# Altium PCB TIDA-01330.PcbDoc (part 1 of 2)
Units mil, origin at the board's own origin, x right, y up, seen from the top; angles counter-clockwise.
Board outline 4950 x 3950 mil, 2 copper layers (Top Layer, Bottom Layer), stack 62.2 mil thick; 84 components, 65 nets, 268 pads, 356 vias.
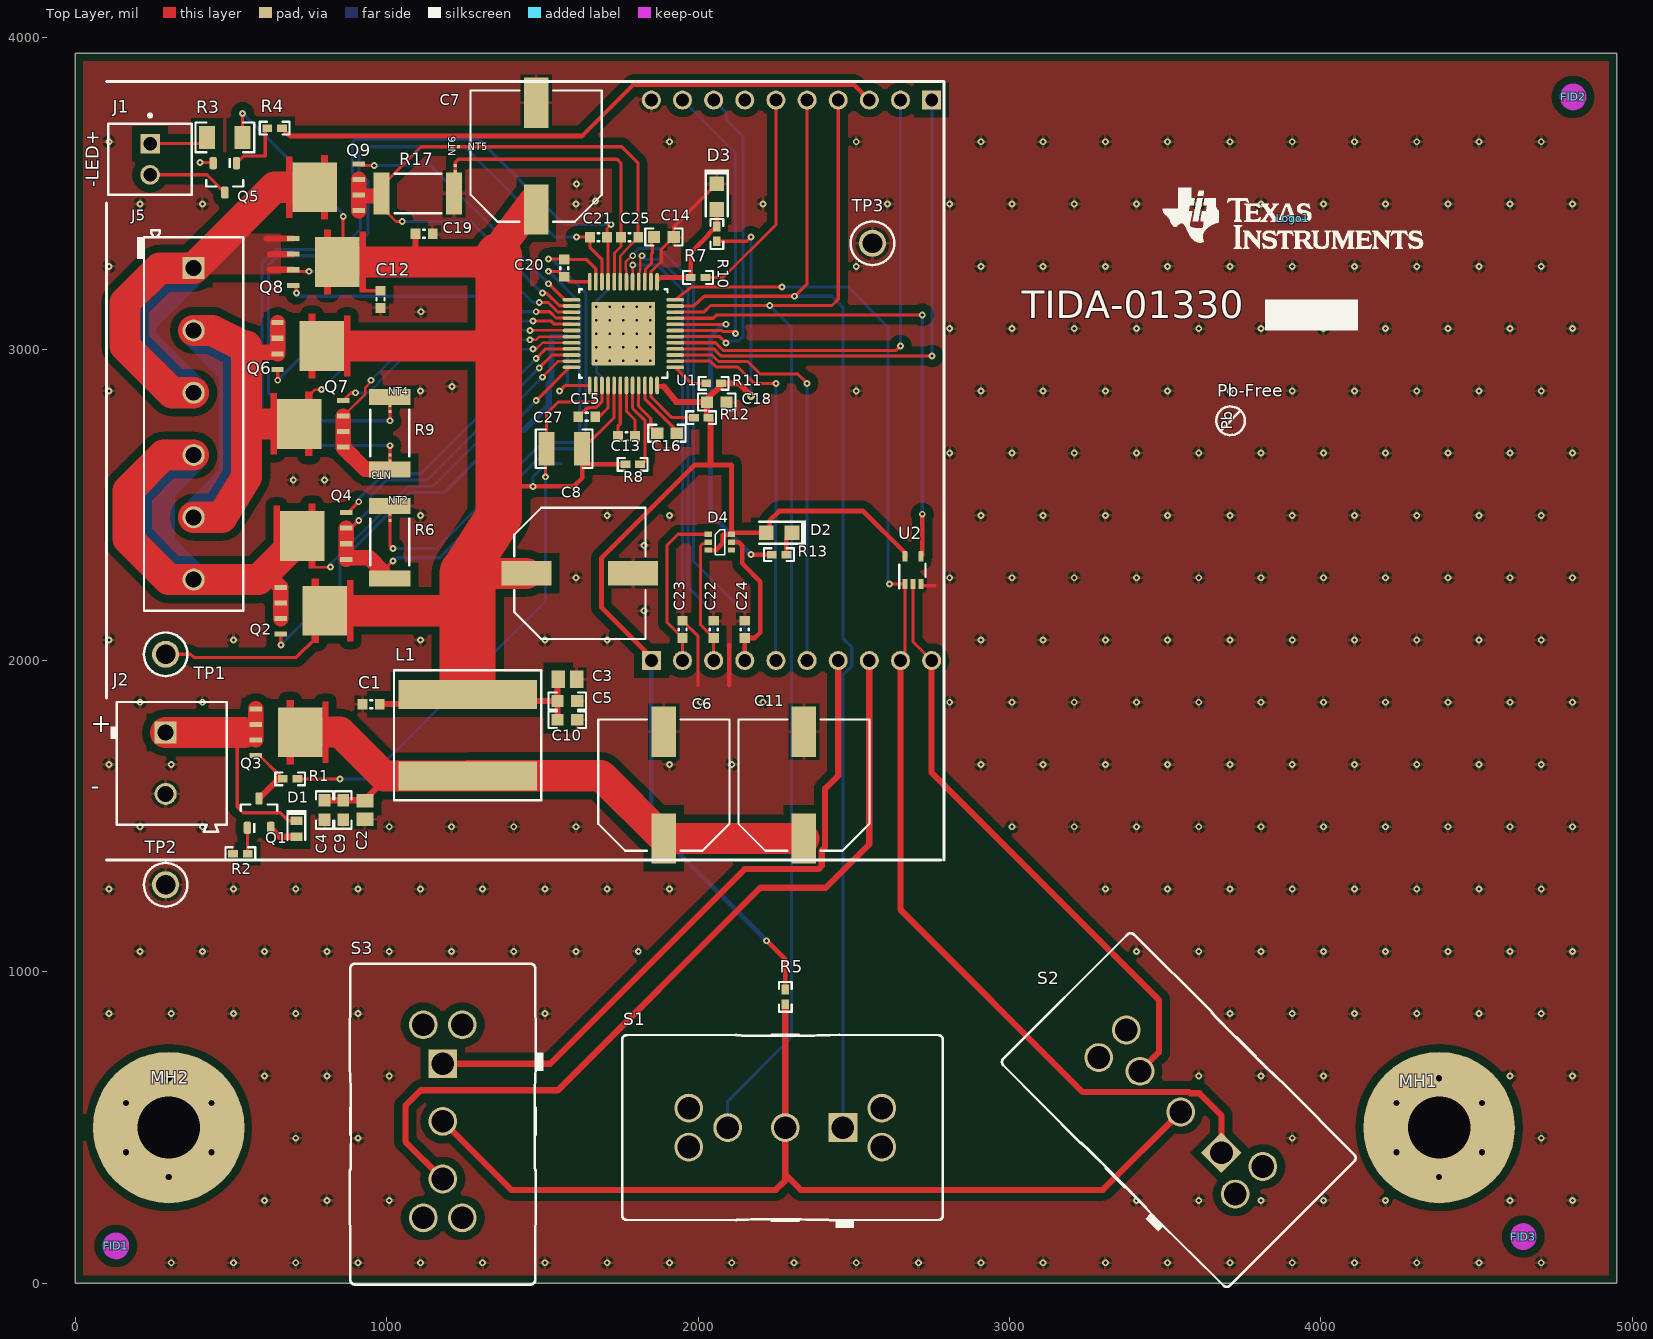
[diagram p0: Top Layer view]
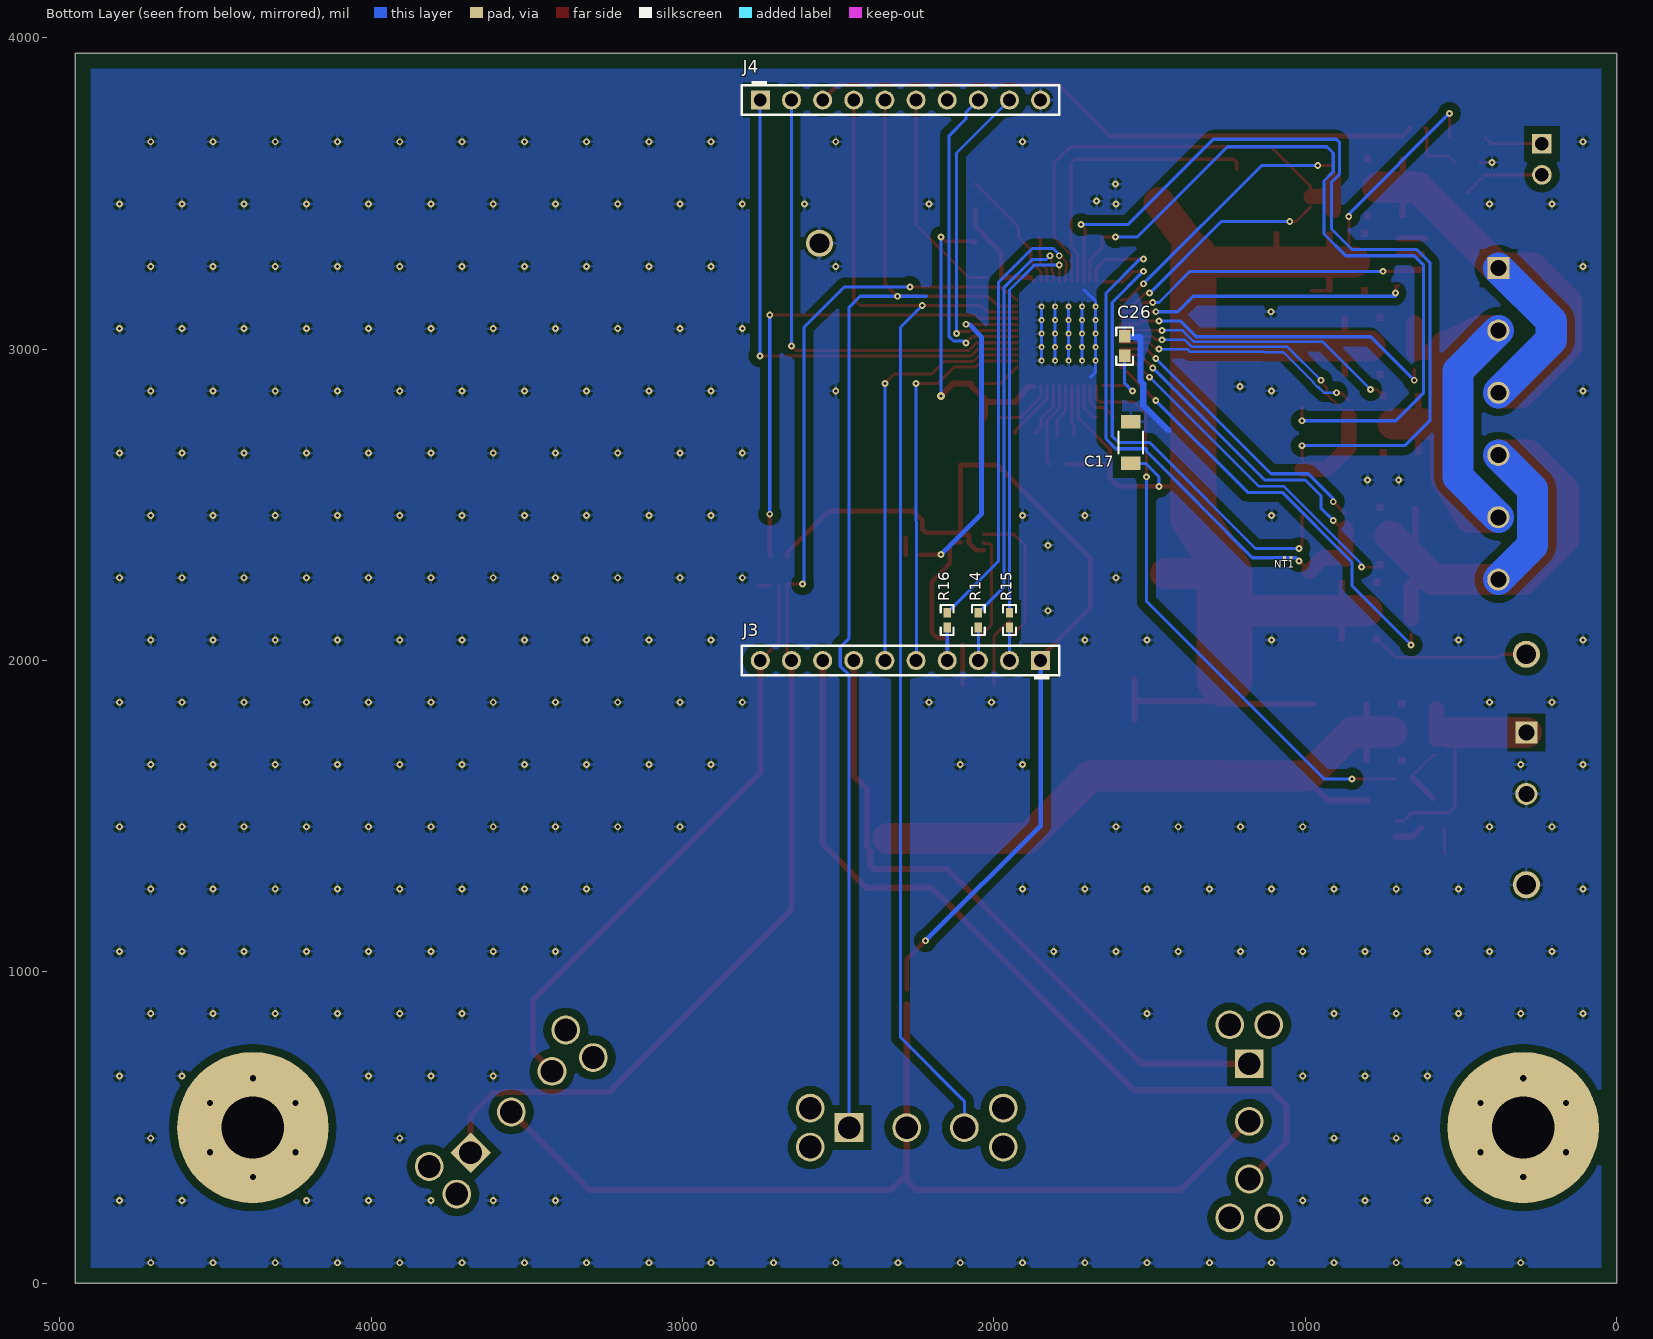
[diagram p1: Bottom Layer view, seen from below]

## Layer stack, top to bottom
Top Solder: solder mask 0.4, Solder Resist, Dk 3.5
Top Layer: signal copper 3.6
Dielectric1: core 55, FR-4, Dk 4.8
Bottom Layer: signal copper 3.6
Bottom Solder: solder mask 0.4, Solder Resist, Dk 3.5

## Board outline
0,0 0,3950 4950,3950 4950,0

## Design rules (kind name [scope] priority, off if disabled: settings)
AcuteAngle [All] p1: minimum=4.50000000000000E+0001 checktracksonly=FALSE
AssemblyTestPointUsage [All] p1: valid=2
BoardOutlineClearance BoardOutlineClearance_MountingHoles [OnCopper and InComponentClass('Mounting Holes')] p1: gap=40
BoardOutlineClearance BoardOutlineClearance_Poly [OnCopper and IsPoly] p2: gap=25
BoardOutlineClearance [OnCopper and Not InComponentClass('Logo') and not InComponentClass('FiducialMark') and not InRegion(1000,500,4000,800) and not InPoly] p3: gap=75
Clearance Clearance_Keepouts [((IsTrack Or IsArc) And Not InPoly) And IsFree and IsKeepOut vs ((IsTrack Or IsArc) And Not InPoly) And IsFree and IsKeepOut] p1: gap=0
Clearance Clearance_Poly [InPolygon] p2: gap=25
Clearance [All] p3: gap=7.87
ComponentClearance ComponentClearance_MountingHoles_FiducialMarks [InComponentClass('Mounting Holes') vs InComponentClass('FiducialMark')] p1: gap=50 collisioncheckmode=3 verticalgap=10 showdistances=FALSE
ComponentClearance ComponentClearance_Shunt [InComponentClass('Header') vs InComponentClass('Shunt')] p2: gap=0 collisioncheckmode=3 verticalgap=0 showdistances=FALSE
ComponentClearance ComponentClearance_Logo [InComponentClass('Logo')] p3: gap=50 collisioncheckmode=3 verticalgap=10 showdistances=FALSE
ComponentClearance ComponentClearance_ScrewToNut [(HasFootprint('NY PMS 440 0025 PH')) vs (HasFootprint('Keystone_1902C'))] p4: gap=5 collisioncheckmode=3 verticalgap=10 showdistances=FALSE
ComponentClearance ComponentClearance_MountingHoles [InComponentClass('Mounting Holes')] p5: gap=250 collisioncheckmode=3 verticalgap=100000 showdistances=FALSE
ComponentClearance ComponentClearance_SmallPassives [HasFootprint('0201*') or HasFootprint('0402*') or HasFootprint('0508') or HasFootprint('0603*') or HasFootprint('0612') or HasFootprint('0805*') or HasFootprint('0815*') or HasFootprint('0830*') or HasFootprint('1206*') or HasFootprint('1210*') or HasFootprint('1808*') or HasFootprint('1812*') or HasFootprint('1825*') or HasFootprint('2010*') or HasFootprint('2220*') or HasFootprint('2225*') or HasFootprint('2512*') or HasFootprint('2728*') or HasFootprint('3518*') vs HasFootprint('0201*') or HasFootprint('0402*') or HasFootprint('0508') or HasFootprint('0603*') or HasFootprint('0612') or HasFootprint('0805*') or HasFootprint('0815*') or HasFootprint('0830*') or HasFootprint('1206*') or HasFootprint('1210*') or HasFootprint('1808*') or HasFootprint('1812*') or HasFootprint('1825*') or HasFootprint('2010*') or HasFootprint('2220*') or HasFootprint('2225*') or HasFootprint('2512*') or HasFootprint('2728*') or HasFootprint('3518*')] p6: gap=14.96 collisioncheckmode=3 verticalgap=10 showdistances=FALSE
ComponentClearance ComponentClearance_THtoSMT [IsThruComponent vs IsSMTComponent] p7: gap=40 collisioncheckmode=3 verticalgap=30 showdistances=FALSE
ComponentClearance ComponentClearance_THtoTH [IsThruComponent vs IsThruComponent] p8: gap=30 collisioncheckmode=3 verticalgap=30 showdistances=FALSE
ComponentClearance [InComponent('NT1')] p9: gap=0 collisioncheckmode=3 verticalgap=10 showdistances=FALSE
DiffPairsRouting [All] p1: maxlimit=100 minlimit=10 mostfreqgap=10 toplayer_minwidth=10 toplayer_maxwidth=15 toplayer_prefwidth=15 bottomlayer_minwidth=10 bottomlayer_maxwidth=15 bottomlayer_prefwidth=15 maxuncoupledlength=1000
FabricationTestPointUsage TestPointUsage [All] p1: valid=2 allowmultiple=FALSE
FabricationTestpoint Testpoint [All] p1: side=3 testpointundercomponent=TRUE minsize=40 maxsize=100 preferedsize=60 minholesize=0 maxholesize=40 preferedholesize=32 testpointgrid=1 allowsidetop=TRUE allowsidebottom=TRUE usegrid=TRUE gridtolerance=0.01
FanoutControl Fanout_LCC [IsLCC] p1: bgadir=Out bgaviamode=Centered fanoutstyle=Auto fanoutdirection=Alternating viagrid=1 // Fanout_LCC (Default Rule)
FanoutControl Fanout_BGA [IsBGA] p2: bgadir=Out bgaviamode=Centered fanoutstyle=Auto fanoutdirection=Alternating viagrid=1 // Fanout_BGA (Default Rule)
FanoutControl Fanout_Default [All] p4: bgadir=Out bgaviamode=Centered fanoutstyle=Auto fanoutdirection=Alternating viagrid=1 // Fanout_Default (Default Rule)
FanoutControl Fanout_Small [(CompPinCount < 5)] p5: bgadir=Out bgaviamode=Centered fanoutstyle=Auto fanoutdirection=OutThenIn viagrid=1 // Fanout_Small (Default Rule)
HoleSize [All] p1: absolutevalues=TRUE maxlimit=251 minlimit=7.87 maxpercent=80.000 minpercent=20.000
MinimumAnnularRing MinimumAnnularRing_ThermalPadVias [IsVia and InAnyComponent] p1: minimumring=5.91
MinimumAnnularRing [All] p2: minimumring=8
MinimumSolderMaskSliver MinimumSolderMaskSliver_Logo [InComponentClass('Logo') vs InComponentClass('Logo')] p1: minsoldermaskwidth=0.7
MinimumSolderMaskSliver [All] p2: minsoldermaskwidth=3.94
PlaneConnect [All] p1: planeconnectstyle=Relief reliefexpansion=10 reliefentries=4 reliefconductorwidth=10 reliefairgap=10
PolygonConnect [All] p1: connectstyle=Relief reliefconductorwidth=10 reliefentries=4 polygonreliefangle="90 Angle" airgapwidth=10
RoomDefinition "TIDA 01330 Schematic" [InComponentClass('TIDA 01330 Schematic')] p1: confinementstyle=ConfineOut formatcopy=TRUE lockcomponents=FALSE outline 5530,7230 5540,7230 5540,7240 5530,7240
RoutingVias ThermalPadVias [IsVia and InAnyComponent] p1: holewidth=7.87 width=19.68 viastyle="Through Hole" minholewidth=7.87 minwidth=19.68 maxholewidth=12.99 maxwidth=23.62
RoutingVias [All] p2: holewidth=16 width=34 viastyle="Through Hole" minholewidth=7.87 minwidth=26 maxholewidth=40 maxwidth=65
SilkToBoardRegionClearance [Not ((IsComment or IsDesignator) And (Hide <> 'False')) and not InRegion(1000,500,4000,800)] p1:
SilkToSilkClearance SilkToSilkClearance_Pb-FreeLogo [(HasFootprint('Pb-Free_Overlay_Medium') OR HasFootprint('Pb-Free_Overlay_Small')) vs (HasFootprint('Pb-Free_Overlay_Medium') OR HasFootprint('Pb-Free_Overlay_Small'))] p1: silktosilkclearance=0
SilkToSilkClearance [All] p2: silktosilkclearance=4
SilkToSolderMaskClearance SilkToComponentPadClearance [IsPad and InAnycomponent] p1: minsilkscreentomaskgap=5 clearancetoexposedcopper=TRUE
SilkToSolderMaskClearance "Silk to Solder Mask Opening" [All] p2: minsilkscreentomaskgap=4 clearancetoexposedcopper=FALSE
SolderMaskExpansion [All] p1: expansion=1.97
Width [All] p1: maxlimit=100 minlimit=6 preferedwidth=10 checkconnectedcopper=TRUE
15 further rules are at their usual default settings.

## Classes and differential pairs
component class FiducialMark: FID1 FID2 FID3 FID?
component class TID_Hardware: FID1 FID2 FID3 FID? Logo1 Logo? MH1 MH2 MH? Pb-Free ZZ?
component class Logo: Logo1
component class "TIDA 01330 Schematic": C1 C2 C3 C4 C5 C6 C7 C8 C9 C10 C11 C12 C13 C14 C15 C16 C17 C18 C19 C20 C21 C22 C23 C24 C25 C26 C27 C28 C29 D1 D2 D3 D4 J1 J2 J3 J4 J5 L1 NT1 NT2 NT3 NT4 NT5 NT6 Q1 Q2 Q3 Q4 Q5 Q6 Q7 Q8 Q9 R1 R2 R3 R4 R5 R6 R7 R8 R9 R10 R11 R12 R13 R14 R15 R16 R17 S1 S2 S3 TP1 TP2 TP3 U1 U2
differential pair S1: +S1_P -S1_N
differential pair S2: +S2_P -S2_N
differential pair S3: +S3_P -S3_N

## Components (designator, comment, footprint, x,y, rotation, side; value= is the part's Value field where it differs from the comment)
C1 "UMK107AB7105KA-T" 0603L 950,1860 r180 top
C2 "GRM21BR71H105KA12L" 0805L 930,1520 r270 top
C3 "GRM21BR71H105KA12L" 0805L 1580,1940 r0 top
C4 "C1608X7R1H104K080AA" 0603 800,1520 r270 top
C5 "C1608X7R1H104K080AA" 0603 1580,1870 r0 top
C6 "EEE-FT1H331AP" SM_RADIAL_G 1890,1600 r90 top
C7 "EEE-FT1H331AP" SM_RADIAL_G 1480,3620 r90 top
C8 "EEE-FT1H331AP" SM_RADIAL_G 1620,2280 r0 top
C9 "C1608X7R1H103K080AA" 0603 860,1520 r270 top
C10 "C1608X7R1H103K080AA" 0603 1580,1810 r0 top
C11 "EEE-FT1H331AP" SM_RADIAL_G 2340,1600 r90 top
C12 "UMK107AB7105KA-T" 0603L 980,3160 r270 top
C13 "C0603C473K1RACTU" 0603L 1770,2720 r180 top
C14 "C1608X7R1C105K080AC" 0603 1890,3360 r180 top
C15 "C0603C473K1RACTU" 0603L 1642.44,2782.44 r0 top
C16 "C1608X7R1C105K080AC" 0603 1900,2730 r0 top
C17 "GRM31CR71H475KA12L" 1206_180 1560,2700 r90 bottom
C18 "C1608X7R1C105K080AC" 0603 2060,2830 r180 top
C19 "UMK107AB7105KA-T" 0603L 1120,3370 r0 top
C20 "GRM188R71C102KA01D" 0603L 1570,3260 r270 top
C21 "GRM188R71C102KA01D" 0603L 1680,3360 r180 top
C22 "GRM188R71C222KA01D" 0603L 2050,2100 r90 top
C23 "GRM188R71C222KA01D" 0603L 1950,2100 r90 top
C24 "GRM188R71C222KA01D" 0603L 2150,2100 r90 top
C25 "GRM188R71C102KA01D" 0603L 1780,3360 r180 top
C26 "C1608X7R1C105K080AC" 0603 1580,3010 r90 bottom
C27 "GRM32ER72A225KA35L" 1210_270 1570,2680 r0 top
D1 "CD0603-S0180" Diode_0603 710,1460 r270 top
D2 "LTST-C170KRKT" LED_LTST-C170_Red 2260,2410 r0 top
D3 "LTST-C170KGKT" LTST-C170KGKT_Green 2060,3490 r90 top
D4 "BAT54CDW-7-F" SOT-363 2070,2380 r0 top
FID1 "Fiducial" Fiducial10-20 130,120 r0 top
FID2 "Fiducial" Fiducial10-20 4810,3810 r0 top
FID3 "Fiducial" Fiducial10-20 4650,150 r0 top
J1 "282834-2" TEC_282834-2 240,3610 r270 top
J2 "691 101 710 002" Wurth_691101710002 290,1670 r270 top
J3 "SSW-110-01-T-S" Samtec_SSW-110-x1-x-S 2300,2000 r0 bottom
J4 "SSW-110-01-T-S" Samtec_SSW-110-x1-x-S 2300,3800 r180 bottom
J5 "1729160" Phoenix_1729160 380,2760 r270 top
L1 "XAL1010-222MEB" XAL1010 1260,1760 r90 top
Logo1 "Texas Instruments" TI_Stacked_Overlay_Small 3910,3420 r0 top
MH1 "MTG_Pads" MTGP_6-32_Washer 4380,500 r0 top
MH2 "MTG_Pads" MTGP_6-32_Washer 300,500 r0 top
NT1 "Net-Tie" Net-Tie_10mil 1056.31,2330 r180 bottom net-tie
NT2 "Net-Tie" Net-Tie_10mil 1010,2460 r90 top net-tie
NT3 "Net-Tie" Net-Tie_10mil 1010,2650 r270 top net-tie
NT4 "Net-Tie" Net-Tie_10mil 1010,2810 r90 top net-tie
NT5 "Net-Tie" Net-Tie_10mil 1220,3650 r180 top net-tie
NT6 "Net-Tie" Net-Tie_10mil 1220,3580 r270 top net-tie
Pb-Free "Pb-Free Symbol" Pb-Free_Overlay_Small 3710,2770 r90 top
Q1 "BC846BLT1G" SOT-23 590,1510 r90 top
Q2 "SQJ858AEP" PowerPAK_SO-8L 770,2160 r0 top
Q3 "SQJ422EP-T1-GE3" PowerPAK_SO-8L 690,1770 r0 top
Q4 "SQJ858AEP" PowerPAK_SO-8L 760,2400 r180 top
Q5 "BC846BLT1G" SOT-23 480,3550 r270 top
Q6 "SQJ858AEP" PowerPAK_SO-8L 760,3010 r0 top
Q7 "SQJ858AEP" PowerPAK_SO-8L 750,2760 r180 top
Q8 "SQJ858AEP" PowerPAK_SO-8L 810,3280 r0 top
Q9 "SQJ858AEP" PowerPAK_SO-8L 800,3520 r180 top
R1 "CRCW040210K0JNED" 0402 690,1620 r180 top
R2 "CRCW040210K0JNED" 0402 530,1380 r180 top
R3 "CRCW1206330RJNEA" 1206 480,3680 r180 top
R4 "CRCW04021K00JNED" 0402 640,3710 r180 top
R5 "CRCW0402330RJNED" 0402 2280,920 r270 top
R6 "CRA2512-FZ-R015ELF" 2512 1010,2380 r270 top
R7 "CRCW040256R0JNED" 0402 2000,3230 r0 top
R8 "CRCW0402100RFKED" 0402 1790,2630 r180 top
R9 "CRA2512-FZ-R015ELF" 2512 1010,2730 r270 top
R10 "CRCW0402470RJNED" 0402 2060,3370 r270 top
R11 "CRCW040210K0JNED" 0402 2050,2890 r0 top
R12 "CRCW040210K0JNED" 0402 2010,2780 r0 top
R13 "CRCW0402470RJNED" 0402 2260,2340 r0 top
R14 "CRCW040256R0JNED" 0402 2050,2130 r90 bottom
R15 "CRCW040256R0JNED" 0402 1950,2130 r90 bottom
R16 "CRCW040256R0JNED" 0402 2150,2130 r90 bottom
R17 "CRA2512-FZ-R015ELF" 2512 1100,3500 r180 top
S1 "7105J3V3QE2" SW_710XJ3V3 2280,500 r180 top
S2 "7105J3V3QE2" SW_710XJ3V3 3550,550 r135 top
S3 "7105J3V3QE2" SW_710XJ3V3 1180,520 r270 top
TP1 "5005" Keystone5005 290,2020 r0 top
TP2 "5006" Keystone5006 290,1280 r0 top
TP3 "5006" Keystone5006 2560,3340 r0 top
U1 "DRV83053EPHPRQ1" PHP0048G_N 1760,3050 r180 top
U2 "SN74AHC1G00DCKR" DCK0005A_N 2690,2290 r90 top

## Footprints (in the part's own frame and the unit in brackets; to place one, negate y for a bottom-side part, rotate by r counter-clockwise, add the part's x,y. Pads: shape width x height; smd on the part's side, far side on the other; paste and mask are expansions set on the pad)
0402 [mm] "0402 from SM-752 data"
  rect 0.8x0.6 smd: 1(-0.6,0) 2(0.6,0)
  silkscreen extent -1.22,-0.52 1.22,0.52, body extent -0.55,-0.3 0.55,0.3, height 0.6
0603 [mm] "0603 from SM-752 data"
  rect 1x0.95 smd: 1(-0.8,0) 2(0.8,0)
  silkscreen extent -1.52,-0.69 1.52,0.69, body extent -0.87,-0.47 0.87,0.47, height 1
0603L [mm] "0603 from SM-752 data"
  rect 0.8x0.85 smd: 1(-0.7,0) 2(0.7,0)
  silkscreen extent -0.07,-0.33 0.07,0.33, body extent -0.87,-0.47 0.87,0.47, height 1
0805L [mm] "0805 from SM-752 data"
  rect 1.1x1.4 smd: 1(-0.75,0) 2(0.75,0)
  body extent -1.1,-0.72 1.1,0.72, height 1.45
1206 [mm] "1206 from SM-752 data"
  rect 1.3x1.85 smd: 1(-1.45,0) 2(1.45,0)
  silkscreen extent -2.4,-1.21 2.4,1.21, body extent -1.7,-0.9 1.7,0.9, height 1.35
1206_180 [mm] "1206_180"
  rect 1.1x1.6 smd: 1(-1.7,0) 2(1.7,0)
  silkscreen extent -0.9,-1 0.9,1, body extent -1.75,-0.95 1.75,0.95, height 1.8
1210_270 [mm] "1210"
  rect 1.3x2.7 smd: 1(-1.45,0) 2(1.45,0)
  silkscreen extent -2.32,-1.57 2.32,1.57, body extent -1.7,-1.35 1.7,1.35, height 2.7
2512 [mm] "Chip Resistor, Body 6.3x3.2mm, IPC Medium Density"
  rect 1.3x3.4 smd: 1(-2.95,0) 2(2.95,0)
  silkscreen extent -1.9,-1.6 1.9,1.6, body extent -3.22,-1.67 3.22,1.67, height 0.71
DCK0005A_N [mm] "SOT353, 5-Leads, Body 2x1.3mm, Pitch 0.65mm, Lead Span 2.1mm, IPC Medium Density"
  rrect25% 0.85x0.4 smd: 1(-1.125,0.65) 2(-1.125,0) 3(-1.125,-0.65) 4(1.125,-0.65) 5(1.125,0.65)
  silkscreen extent -1.48,-1.02 0.55,1.1, body extent -1.14,-1 1.14,1, height 0.95
Diode_0603 [mm] "Based on Bourns recommended land pattern Rev 10/09"
  rect 0.7x1 smd: 1(-0.65,0) 2(0.65,0)
  silkscreen extent -1.5,-0.8 0.9,0.8, body extent -0.9,-0.5 0.9,0.5, height 0.85
Fiducial10-20 [mm]
  round 1 smd mask+0.5: 1(0,0)
  Top Layer keep-out circle w1.178: c0,0 r0.5
Keystone5005 [mil] "Keystone Compact loops"
  round 87 hole 63: 1(0,0)
  silkscreen extent -70,-70 70,70, body extent -63,-63 62,63, height 225
Keystone5006 [mil] "Keystone Compact loops"
  round 87 hole 63: 1(0,0)
  silkscreen extent -70,-70 70,70, body extent -63,-63 62,63, height 225
LED_LTST-C170_Red [mm] "LITE-ON"
  rect 1.2x1.2 smd: 1(-1.05,0) 2(1.05,0)
  silkscreen extent -1.6,-1 2.2,1, body extent -1.05,-0.67 1.05,0.67, height 1.1
LTST-C170KGKT_Green [mm] "LITE-ON"
  rect 1.2x1.2 smd: 1(-1.05,0) 2(1.05,0)
  silkscreen extent -1.6,-1 2.2,1, body extent -1.05,-0.67 1.05,0.67, height 1.1
MTGP_6-32_Washer [mm] "6-32 Mounting Hole, Plated, for Flat Washer"
  round 12.35 hole 5.08: 1(0,0)
Net-Tie_10mil [mil] "10mil net tie, no solder mask opening, no solder paste"
  rect 10x10 smd paste-5 mask-5: 1(-10,0) 2(10,0)
  Top Layer region: -6,5 6,5 6,-5 -6,-5
Pb-Free_Overlay_Small [mil]
  silkscreen extent -46,-46 46,46
Phoenix_1729160 [mm] "Phoenix Contact"
  rect 1.8x1.8 hole 1.3 paste+0: 1(-12.7,0)
  round 1.8 hole 1.3 paste+0: 2(-7.62,0) 3(-2.54,0) 4(2.54,0) 5(7.62,0) 6(12.7,0)
  silkscreen extent -15.81,-4.63 15.24,4.05, body extent -15.81,-4.05 15.24,4.05, height 10.01
PHP0048G_N [mm] "QFP, 48-Leads, Body 7x7mm, Pitch 0.5mm, Thermal Pad 5.17X5.17mm, IPC Medium Density"
  oval 1.45x0.3 smd: 1(-4.225,2.75) 2(-4.225,2.25) 3(-4.225,1.75) 4(-4.225,1.25) 5(-4.225,0.75) 6(-4.225,0.25) 7(-4.225,-0.25) 8(-4.225,-0.75) 9(-4.225,-1.25) 10(-4.225,-1.75) 11(-4.225,-2.25) 12(-4.225,-2.75) 25(4.225,-2.75) 26(4.225,-2.25) 27(4.225,-1.75) 28(4.225,-1.25) 29(4.225,-0.75) 30(4.225,-0.25) 31(4.225,0.25) 32(4.225,0.75) 33(4.225,1.25) 34(4.225,1.75) 35(4.225,2.25) 36(4.225,2.75)
  oval 0.3x1.45 smd: 13(-2.75,-4.225) 14(-2.25,-4.225) 15(-1.75,-4.225) 16(-1.25,-4.225) 17(-0.75,-4.225) 18(-0.25,-4.225) 19(0.25,-4.225) 20(0.75,-4.225) 21(1.25,-4.225) 22(1.75,-4.225) 23(2.25,-4.225) 24(2.75,-4.225) 37(2.75,4.225) 38(2.25,4.225) 39(1.75,4.225) 40(1.25,4.225) 41(0.75,4.225) 42(0.25,4.225) 43(-0.25,4.225) 44(-0.75,4.225) 45(-1.25,4.225) 46(-1.75,4.225) 47(-2.25,4.225) 48(-2.75,4.225)
  rrect2% 5.17x5.17 smd: 49(0,0)
  silkscreen extent -3.6,-3.6 3.6,3.6, body extent -4.51,-4.51 4.51,4.51, height 1.2
PowerPAK_SO-8L [mm] "based on Vishay recommended land pattern Document 63818 Feb 7, 2012"
  rect 1x0.41 smd: 1(-2.805,1.905) 2(-2.805,0.635) 3(-2.805,-0.635) 4(-2.805,-1.905)
  rect 3.63x4.061 smd: 5(0.805,0)
  Top Layer region: 2.615,-2.5 3.125,-2.5 3.125,2.5 2.615,2.5
  Top Layer region: -0.297,2.03 0.298,2.03 0.298,2.64 -0.297,2.64
  Top Layer region: -0.298,-2.64 0.298,-2.64 0.298,-2.03 -0.298,-2.03
  body extent -3.07,-2.57 3.08,2.57, height 1.21
Samtec_SSW-110-x1-x-S [mm] "Receptacle, 2.54mm, 10x1, TH"
  rect 1.55x1.55 hole 1.04: 1(-11.43,0)
  round 1.55 hole 1.04: 2(-8.89,0) 3(-6.35,0) 4(-3.81,0) 5(-1.27,0) 6(1.27,0) 7(3.81,0) 8(6.35,0) 9(8.89,0) 10(11.43,0)
  silkscreen extent -12.95,-1.21 12.95,1.55, body extent -12.95,-1.21 12.95,1.21, height 8.51
SM_RADIAL_G [mm] "10 x 10.2mm:  Panasonic G"
  rect 4.1x2 smd: 1(-4.35,0) 2(4.35,0)
  silkscreen extent -5.35,-5.35 5.35,5.35, body extent -5.25,-5.25 5.25,5.25, height 10.5
SOT-23 [mm] "SOT23, 3-Leads, Body 2.9x1.3mm, Pitch 0.95mm, Lead Span 2.5mm, IPC Medium Density"
  rrect50% 1x0.6 smd: 1(-1.2,0.95) 2(-1.2,-0.95) 3(1.2,0)
  silkscreen extent -1.63,-1.5 0.7,1.5, body extent -1.16,-1.45 1.21,1.45, height 1
SOT-363 [mm]
  rect 0.6x0.42 smd mask+0.051: 1(-0.95,0.65) 2(-0.95,0) 3(-0.95,-0.65) 4(0.95,-0.65) 5(0.95,0) 6(0.95,0.65)
  silkscreen extent -0.38,-1.02 0.38,1.02, body extent -1.1,-1.1 1.1,1.1, height 1.12
SW_710XJ3V3 [mm] "TH, 3-Leads, Body 15.75x8.13mm, Pitch 4.7mm"
  rect 2.35x2.35 hole 1.85: 1(-4.7,0)
  round 2.35 hole 1.85: 2(0,0) 3(4.7,0) S1(-7.875,1.59) S2(-7.875,-1.59) S3(7.875,-1.59) S4(7.875,1.59)
  silkscreen extent -12.85,-7.57 13.31,8.2, body extent -12.85,-7.57 13.31,7.58, height 26.51
TEC_282834-2 [mm] "TEC"
  rect 1.6x1.6 hole 1.1: 1(-1.27,0)
  round 1.6 hole 1.1: 2(1.27,0)
  silkscreen extent -3.66,-3.4 2.9,3.4, body extent -2.77,-3.25 2.77,3.25, height 10.01
TI_Stacked_Overlay_Small [mil]
  silkscreen extent -418,-98 418,98
Wurth_691101710002 [mm] "Terminal Block, 5 mm, 2x1, TH"
  rect 1.8x1.8 hole 1.3: 1(-2.5,0)
  round 1.8 hole 1.3: 2(2.5,0)
  silkscreen extent -5,-4.5 5.6,5, body extent -5.6,-4 5.6,5, height 12.5
XAL1010 [mm] "COILCRAFT"
  rect 2.38x11.31 smd: 1(-3.325,0) 2(3.325,0)
  silkscreen extent -5.3,-6 5.3,6, body extent -5.25,-5.9 5.25,5.9, height 10

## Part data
C1 C12 C19: "CAP, CERM, 1 µF, 50 V, +/- 10%, X7R, 0603"
C2 C3: "CAP, CERM, 1uF, 50V, +/-10%, X7R, 0805"
C4 C5: "CAP, CERM, 0.1 µF, 50 V, +/- 10%, X7R, 0603"
C6 C7 C8 C11: library part EEE-FC1H221P, "CAP, AL, 330 µF, 50 V, +/- 20%, 0.3 ohm, SMD"
C9 C10: "CAP, CERM, 0.01 µF, 50 V, +/- 10%, X7R, 0603"
C13 C15: library part GRM188R72A104KA35D, "CAP, CERM, 0.047uF, 100V, +/-10%, X7R, 0603"
C14 C16 C18 C26: "CAP, CERM, 1 µF, 16 V, +/- 10%, X7R, 0603"
C17: "CAP, CERM, 4.7 µF, 50 V, +/- 10%, X7R, 1206"
C20 C21 C25: "CAP, CERM, 1000pF, 16V, +/-10%, X7R, 0603"
C22 C23 C24: "CAP, CERM, 2200pF, 16V, +/-10%, X7R, 0603"
C27: "CAP, CERM, 2.2 µF, 100 V, +/- 10%, X7R, 1210"
D1: "Diode, Switching, 90V, 0.1A, 0603 Diode"
D2: "LED, Red, SMD"
D3: "LED, Green, SMD"
D4: "Diode, Schottky, 30 V, 0.2 A, SOT-363"
FID1 FID2 FID3: "Fiducial mark.  There is nothing to buy or mount."
J1: "Terminal Block, 2x1, 2.54mm, TH"
J2: "Terminal Block, 5 mm, 2x1, Tin, TH"
J3 J4: "Receptacle, 2.54mm, 10x1, Tin, TH"
J5: "Terminal Block, 6x1, 5.08mm, Th"
L1: "Inductor, Shielded, Composite, 2.2 µH, 32 A, 0.00255 ohm, SMD"
Logo1: library part TI_Logo, "Texas Instrument Corporate Signature"
MH1 MH2: library part "Mounting Hole (Imperial) with Pads", "PCB Mounting Hole"
NT1 NT2 NT3 NT4 NT5 NT6: "Single point connection between nets."
Pb-Free: library part Pb-Free
Q1 Q5: library part "BC846BLT1G, ON Semiconductor", "Transistor, NPN, 65V, 0.1A, SOT-23"
Q2 Q4 Q6 Q7 Q8 Q9: library part SQJ858AEP-T1-GE3, "MOSFET, N-CH, 40 V, 58 A, PowerPAK_SO-8L"
Q3: "MOSFET, N-CH, 40 V, 75 A, PowerPAK_SO-8L"
R1 R2 R11 R12: "RES, 10 k, 5%, 0.063 W, 0402"
R3: "RES, 330, 5%, 0.25 W, 1206"
R4: "RES, 1.0 k, 5%, 0.063 W, 0402"
R5: "RES, 330, 5%, 0.063 W, 0402"
R6 R9 R17: "RES, 0.015, 1%, 3 W, 2512"
R7 R14 R15 R16: "RES, 56, 5%, 0.063 W, 0402"
R8: "RES, 100, 1%, 0.063 W, 0402"
R10 R13: "RES, 470, 5%, 0.063 W, 0402"
S1 S2 S3: "Switch, SPDT, Mom-Off-Mom, 3 Pos, 5 A, 28 VDC, TH"
TP1: "Test Point, Compact, Red, TH"
TP2 TP3: "Test Point, Compact, Black, TH"
U1: "Three Phase Automotive Gate Driver with Three Integrated Current Shunt Amplifiers and Voltage Regulator, PHP0048G"
U2: "SINGLE 2-INPUT POSITIVE-NAND GATE, DCK0005A (SOT-5)"

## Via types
v1: diameter 22, hole 10, Top Layer to Bottom Layer, 318 vias
v2: diameter 19.68, hole 7.87, Top Layer to Bottom Layer, 25 vias
v3: diameter 39.37, hole 19.68, Top Layer to Bottom Layer, 12 vias
v4: diameter 26, hole 10, Top Layer to Bottom Layer, 1 vias

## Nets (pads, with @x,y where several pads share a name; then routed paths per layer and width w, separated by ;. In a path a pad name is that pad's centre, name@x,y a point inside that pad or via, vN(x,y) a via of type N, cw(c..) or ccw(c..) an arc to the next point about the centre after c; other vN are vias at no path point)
3P3V: C18.2 D2.1 D4.3 D4.6 J3.1 R5.1 R10.2 R11.2 R12.2 U1.48 U2.5 | length 4368
  Top Layer w10: R10.2@2060,3346.38 2156.38,3346.38 v1(2170,3360)
  Top Layer w15: J3.1@1850,2000 1850,2010 1690,2170 1690,2330 1987.82,2627.82 2040,2627.82 2107.4,2627.82 D4.6@2107.4,2405.59 ; U1.48@1870,2880 1890,2880 ; D4.3@2032.6,2354.41 2056.22,2354.41 2080.22,2378.41 2080.22,2403.64 D4.6@2105.45,2403.64 ; R10.2@2060,3346.38 R10.2@2063.62,3342.76 ; D4.6@2111.81,2410 D2.1@2218.66,2410 2230,2421.34 2230,2450 2260,2480 2530,2480 2664.41,2345.59 U2.5@2664.41,2334.29 ; v1(2220,1100) 2280,1040 R5.1@2280,943.62
  Top Layer w20: 1890,2880 1930,2830 C18.2@2028.5,2830 2028.5,2785.12 R12.2@2033.62,2780 2040,2773.62 2040,2627.82 ; C18.2@2028.5,2838.5 R11.2@2076.38,2886.38 ; R11.2@2073.62,2890 2130,2890 v4(2170,2850)
  Bottom Layer w10: v4(2170,2850) v1(2170,3360)
  Bottom Layer w15: J3.1@1850,2000 1850,1470 v1(2220,1100)
AH: J3.5 U1.2 | length 1241.8
  Top Layer w10: U1.2@1926.34,2961.42 2038.99,2961.42 2057.9,2942.5 2127.5,2942.5 2180,2890 v1(2250,2890)
  Bottom Layer w10: J3.5@2248.58,2001.42 v1(2250,2890)
AL: J3.6 U1.3 | length 1355.2
  Top Layer w10: U1.3@1926.34,2981.1 2044.58,2981.1 2065.3,2960.38 2159.62,2960.38 2200,2920 2320,2920 v1(2350,2890) v1@2350,2893.76
  Bottom Layer w10: J3.6@2350,2000 v1(2350,2890)
AVDD: C14.2 U1.15 | length 159.1
  Top Layer w10: U1.15@1828.9,3216.34 1829.8,3217.24 1829.8,3246.76 1830.71,3247.66 1830.71,3255.99 1850,3275.28 1850,3306.24 1853.87,3310.11 1853.87,3329.89 1850,3333.76 1850,3351.5 C14.2@1858.5,3360
BACK: J4.4 S1.3 U1.10 | length 3934.2
  Top Layer w10: U1.10@1926.34,3118.9 2020,3120 2040,3140 2430,3140 2450,3160 J4.4@2450,3800
  Bottom Layer w10: S1.3@2094.96,500 2094.96,584.96 2300,790 2300,3070 v1(2230,3140)
BH: J4.1 U1.4 | length 1654.7
  Top Layer w10: U1.4@1926.34,3000.79 2050.17,3000.79 2072.71,2978.25 v1(2751.75,2978.25)
  Bottom Layer w10: v1(2751.75,2978.25) J4.1@2751.75,3798.25
BL: J4.2 U1.5 | length 1529.5
  Top Layer w10: U1.5@1926.34,3020.47 2055.76,3020.47 2080.11,2996.13 2636.13,2996.13 v1(2650,3010)
  Bottom Layer w10: v1(2650,3010) J4.2@2650,3800
CH: J4.8 U1.6 | length 1033
  Top Layer w10: U1.6@1926.34,3040.16 2069.84,3040.16 v1(2090,3020)
  Bottom Layer w10: J4.8@2050,3800 2090,3760 2090,3739.15 2143.87,3685.28 2143.87,3040.11 2129.89,3026.13 2096.13,3026.13 v1(2090,3020)
CL: J4.9 U1.7 | length 1009.5
  Top Layer w10: U1.7@1926.34,3059.84 2076.39,3059.84 2080.11,3056.13 v1@2113.87,3056.13
  Bottom Layer w10: J4.9@1950,3800 2120,3630 v1(2120,3050)
DOWN: J3.8 S3.3 | length 2712.7
  Top Layer w20: S3.3@1180,334.96 1060,454.96 1060,570 1110,620 1550,620 2200,1270 2410,1270 2550,1410 J3.8@2550,2000
DVDD: C16.2 U1.46 | length 196.2
  Top Layer w10: U1.46@1828.9,2883.66 1828.9,2841.1 1931.5,2738.5 C16.2@1931.5,2730
EN_GATE: R11.1 U1.1 | length 121.5
  Top Layer w10: U1.1@1926.34,2941.73 1978.07,2890 R11.1@2026.38,2890
FWD: J4.5 S1.1 U1.11 | length 3962.9
  Top Layer w10: U1.11@1926.34,3138.58 1984.33,3138.58 1985.75,3140 2020,3170 v1(2310,3170) 2350,3210 J4.5@2350,3800
  Bottom Layer w10: 2217.17,3170 2430,3170 2465.04,3134.96 2465.04,2071.73 2493.39,2043.39 2493.39,1982.03 2465.04,1953.68 S1.1@2465.04,500
GH_A: Q2.4 U1.36 | length 1382.2
  Top Layer w10: v1@659.57,2050.43 Q2.4@659.57,2085 ; v1(1480,2834.72) 1587.01,2941.73 U1.36@1593.66,2941.73
  Bottom Layer w10: v1(660,2050) 850,2240 850,2316.14 1073.86,2540 1185.28,2540 v1(1480,2834.72)
GH_B: Q6.4 U1.29 | length 1061.9
  Top Layer w10: Q6.4@649.57,2935 650,2934.57 v1(650,2900) ; v1(1470,3090) 1528.35,3090 1537.92,3080.43 1592.76,3080.43 U1.29@1593.66,3079.53
  Bottom Layer w10: v1(650,2900) 790,3040 1350,3040 1400,3090 v1(1470,3090)
GH_C: Q8.4 U1.28 | length 952.3
  Top Layer w10: Q8.4@699.57,3205 710,3194.57 ; v1(710,3180) Q8.4@710,3204.57 ; v1(1480,3120) 1523.63,3120 1543.51,3100.12 1592.76,3100.12 U1.28@1593.66,3099.21
  Bottom Layer w10: v1@710,3170 1360,3170 1410,3120 v1(1480,3120)
GL_A: Q4.4 U1.33 | length 946.9
  Top Layer w10: Q4.4@870.43,2475 875,2475 v1(910,2510) ; v1(1480,2970) 1510.79,3000.79 U1.33@1593.66,3000.79
  Bottom Layer w10: v1(910,2510) 910,2520 990,2600 1110,2600 v1(1480,2970)
GL_B: Q7.4 U1.32 | length 811.4
  Top Layer w8: v1(1470,3000) 1480,3000 1500.47,3020.47 U1.32@1593.66,3020.47
  Top Layer w10: Q7.4@860.43,2835 885.43,2860 v1(900,2860)
  Bottom Layer w8: v1(900,2860) 940,2860 957.13,2877.13 959.47,2877.13 972.87,2890.53 972.87,2892.87 1070,2990 1130,2990 1131.38,2991.38 1370.14,2991.38 1378.76,3000 v1(1470,3000)
GL_C: Q9.4 U1.25 | length 864.1
  Top Layer w10: Q9.4@910.43,3595 915.43,3590 v1(960,3590) ; v1(1520,3210) 1571.73,3158.27 U1.25@1593.66,3158.27
  Bottom Layer w10: v1(960,3590) 1140,3590 v1(1520,3210)
GND: C1.2 C2.2 C3.2 C4.2 C5.2 C6.2 C7.2 C8.2 C9.2 C10.2 C11.2 C12.2 C14.1 C16.1 C17.2 C18.1 C19.2 C22.2 C23.2 C24.2 C26.2 D3.2 J2.2 J4.10 NT2.2 NT4.2 NT6.2 Q5.2 R2.2 R6.1 R9.1 R17.1 TP2.1 TP3.1 U1.14 U1.45 U1.49 U2.3 | length 2403.4
  Top Layer w10: v1(400,3600) Q5.2@439.84,3600 ; U1.45@1809.21,2883.66 1809.21,2816.06 1847.87,2777.4 1847.87,2750.63 C16.1@1868.5,2730 ; U1.14@1848.58,3216.34 1848.58,3248.58 1881.5,3281.5 1881.5,3320 C14.1@1921.5,3360 1921.5,3392.83 D3.2@2060,3531.34 ; C23.2@1950,2127.56 2000,2077.56 2000,1920 ; U2.3@2715.59,2245.71 2721.3,2240 2760,2240
  Top Layer w15: 2100,1921.47 2100,2050
  Bottom Layer w10: 1690,2910 1673.39,2926.61 v2(1673.39,2963.39) v2(1673.39,3006.69) v2(1673.39,3050) v2(1673.39,3093.31) v2(1673.39,3136.61) 1673.39,3153.39 1710,3190 ; v2(1716.69,2963.39) v2(1716.69,3006.69) v2(1716.69,3050) v2(1716.69,3093.31) v2(1716.69,3136.61) ; v2(1760,2963.39) v2(1760,3006.69) v2(1760,3050) v2(1760,3093.31) v2(1760,3136.61) ; v2(1803.31,2963.39) v2(1803.31,3006.69) v2(1803.31,3050) v2(1803.31,3093.31) v2(1803.31,3136.61) ; v2(1846.61,2963.39) v2(1846.61,3006.69) v2(1846.61,3050) v2(1846.61,3093.31) v2(1846.61,3136.61)
  Bottom Layer w20: 1440,2740 1520,2820 1520,2889.17 1528.87,2898.04 1528.87,3038.87 C26.2@1577.38,3038.87
  other v1: 308,66 508,66 708,66 908,66 1108,66 1308,66 1508,66 1708,66 1908,66 2108,66 2308,66 2508,66 2708,66 2908,66 3108,66 3308,66 3508,66 3708,66 3908,66 4108,66 4308,66 4508,66 4708,66 608,266 808,266 1008,266 3408,266 3608,266 3808,266 4008,266 4208,266 4608,266 4808,266 708,466 908,466 3908,466 4708,466 608,666 808,666 1008,666 3608,666 3808,666 4008,666 4608,666 4808,666 108,866 308,866 508,866 708,866 908,866 1508,866 3708,866 3908,866 4108,866 4308,866 4508,866 4708,866 208,1066 408,1066 608,1066 808,1066 1008,1066 1208,1066 1408,1066 1608,1066 1808,1066 3408,1066 3608,1066 3808,1066 4008,1066 4208,1066 4408,1066 4608,1066 4808,1066 108,1266 508,1266 708,1266 908,1266 1108,1266 1308,1266 1508,1266 1708,1266 1908,1266 3308,1266 3508,1266 3708,1266 3908,1266 4108,1266 4308,1266 4508,1266 4708,1266 208,1466 408,1466 1008,1466 1208,1466 1408,1466 1608,1466 3008,1466 3208,1466 3408,1466 3608,1466 3808,1466 4008,1466 4208,1466 4408,1466 4608,1466 4808,1466 108,1666 308,1666 1908,1666 2108,1666 2908,1666 3108,1666 3308,1666 3508,1666 3708,1666 3908,1666 4108,1666 4308,1666 4508,1666 4708,1666 208,1866 408,1866 2008,1866 2208,1866 2808,1866 3008,1866 3208,1866 3408,1866 3608,1866 3808,1866 4008,1866 4208,1866 4408,1866 4608,1866 4808,1866 108,2066 508,2066 1108,2066 1508,2066 1708,2066 2908,2066 3108,2066 3308,2066 3508,2066 3708,2066 3908,2066 4108,2066 4308,2066 4508,2066 4708,2066 1826.69,2160 1608,2266 2808,2266 3008,2266 3208,2266 3408,2266 3608,2266 3808,2266 4008,2266 4208,2266 4408,2266 4608,2266 4808,2266 1826.69,2370 1108,2466 1708,2466 1908,2466 2908,2466 3108,2466 3308,2466 3508,2466 3708,2466 3908,2466 4108,2466 4308,2466 4508,2466 4708,2466 700,2580 800,2580 2808,2666 3008,2666 3208,2666 3408,2666 3608,2666 3808,2666 4008,2666 4208,2666 4408,2666 4608,2666 4808,2666 108,2866 1108,2866 2508,2866 2908,2866 3108,2866 3308,2866 3508,2866 3708,2866 3908,2866 4108,2866 4308,2866 4508,2866 4708,2866 1210,2880 2808,3066 3008,3066 3208,3066 3408,3066 3608,3066 3808,3066 4008,3066 4208,3066 4408,3066 4608,3066 4808,3066 1110,3120 108,3266 2508,3266 2908,3266 3108,3266 3308,3266 3508,3266 3708,3266 3908,3266 4108,3266 4308,3266 4508,3266 4708,3266 208,3466 408,3466 1608,3466 2208,3466 2608,3466 2808,3466 3008,3466 3208,3466 3408,3466 3608,3466 3808,3466 4008,3466 4208,3466 4408,3466 4608,3466 4808,3466 1670,3475.35 1610,3530 108,3666 1908,3666 2508,3666 2908,3666 3108,3666 3308,3666 3508,3666 3708,3666 3908,3666 4108,3666 4308,3666 4508,3666 4708,3666
ISNS_A: C22.1 D4.2 J3.3 R14.1 | length 524.1
  Top Layer w10: D4.2@2032.6,2380 2032.6,2375.55 2015.45,2375.55 2007.91,2368.01 2007.91,2114.53 C22.1@2050,2072.44 J3.3@2050,2000
  Bottom Layer w10: J3.3@2050,2000 R14.1@2050,2106.38
ISNS_B: C23.1 D4.1 J3.2 R15.1 | length 644.4
  Top Layer w10: J3.2@1950,2000 C23.1@1950,2072.44 1900,2122.44 1900,2370 1935.59,2405.59 D4.1@2032.6,2405.59
  Bottom Layer w10: J3.2@1950,2000 R15.1@1950,2106.38
ISNS_C: C24.1 D4.5 J3.4 R16.1 | length 577.7
  Top Layer w15: D4.5@2107.4,2380 2130,2380 2141.63,2368.37 2141.63,2311.63 2200,2253.25 2200,2090 2182.44,2072.44 C24.1@2150,2072.44 J3.4@2150,2000
  Bottom Layer w10: J3.4@2150,2000 R16.1@2150,2106.38
LED: J4.3 R4.1 | length 1986.1
  Top Layer w15: R4.1@663.62,3710 688.99,3684.63 1627.13,3684.63 1792.5,3850 2500,3850 J4.3@2550,3800
LEDANODE: J1.1 R3.2 | length 191.2
  Top Layer w10: J1.1@240,3660 402.91,3660 R3.2@422.91,3680
LEDCATHODE: J1.2 Q5.3 | length 263.7
  Top Layer w10: J1.2@240,3560 422.76,3560 Q5.3@480,3502.76
MOT_A: J5.4 J5.6 Q2.1 Q2.2 Q2.3 Q4.5 U1.35 | length 2870.6
  Top Layer w8: 760,2300 v1(820,2300) ; v1(1500,2910) 1550,2960 1550,2961.42 U1.35@1593.66,2961.42
  Top Layer w50: 588.31,2260 634.57,2260 Q2.1@659.57,2235 Q2.2@659.57,2185 Q2.3@659.57,2135
  Top Layer w100: J5.4@380,2660 283.63,2660 170,2546.37 170,2390 300,2260 J5.6@380,2260 588.31,2260 Q4.5@728.31,2400
  Bottom Layer w8: v1(820,2300) 820,2310 1070,2560 1150,2560 v1(1500,2910)
  Bottom Layer w100: J5.6@380,2260 270,2370 270,2550 J5.4@380,2660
